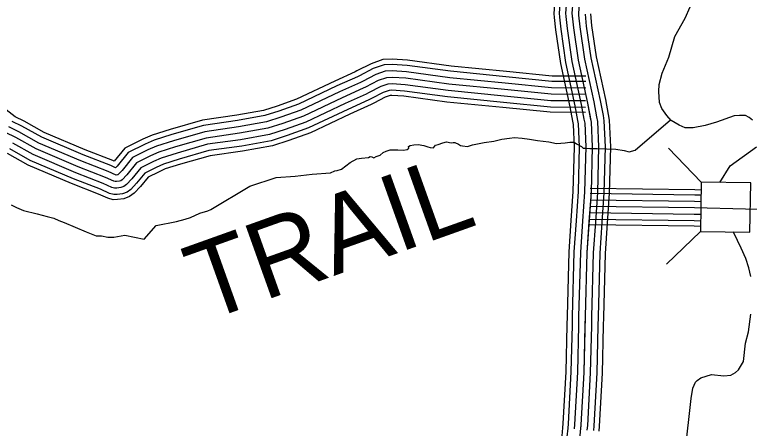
# Model space of a CAD drawing. Extents: x 1551132 to 1791609, y 378168 to 563823.
# Drawn here: x 1641403 to 1644933, y 435995 to 437985 of the extents above; entities that cross this region are included whole.
import ezdxf

# ---------------------------------------------------------------- set-up
doc = ezdxf.new("R2010")
doc.units = 0
for name, color, linetype in [('DESIGN - ROW - Right-of-Way and Easement Labels', 7, 'Continuous'), ('DESIGN - TRANSPORTATION - Text', 7, 'Continuous'), ('SURVEY - CONTROL with Text', 7, 'Continuous'), ('SURVEY - DRAINAGE - Storm Sewer', 7, 'Continuous'), ('SURVEY - TRANSPORTATION - Roads', 7, 'Continuous')]:
    doc.layers.add(name, color=color, linetype=linetype)

msp = doc.modelspace()

# ---------------------------------------------------------------- linework, layer by layer
at = {"layer": 'DESIGN - TRANSPORTATION - Text'}
for points in [[(1644947.992, 437477.501), (1644932.168, 437489.718), (1644914.31, 437499.96), (1644886.335, 437500.319), (1644860.328, 437498.644), (1644775.988, 437467.651), (1644721.823, 437452.309), (1644663.724, 437441.017), (1644624.683, 437441.342), (1644595.934, 437453.892), (1644558.251, 437476.409), (1644536.585, 437500.718), (1644513.019, 437533.069), (1644501.42, 437563.262), (1644498.095, 437615.388), (1644500.536, 437649.414), (1644515.219, 437703.315), (1644546.21, 437781.051), (1644575.476, 437880.845), (1644624.575, 437968.372), (1644649.258, 438022.149)], [(1642345.145, 437047.822), (1642533.14, 437159.633), (1642659.146, 437201.435), (1642751.11, 437208.435), (1642833.108, 437217.543), (1642921.073, 437224.585), (1642941.156, 437234.377), (1642953.164, 437236.252), (1642973.205, 437242.036), (1643015.504, 437273.612), (1643047.653, 437291.279), (1643069.67, 437295.046), (1643103.669, 437298.679), (1643111.702, 437302.596), (1643119.668, 437300.504), (1643129.61, 437296.387), (1643139.66, 437302.287), (1643159.726, 437310.071), (1643173.842, 437321.938), (1643187.884, 437327.788), (1643207.95, 437335.58), (1643243.899, 437335.18), (1643271.832, 437332.872), (1643289.856, 437336.68), (1643297.914, 437342.597), (1643296.006, 437350.63), (1643304.056, 437356.547), (1643322.055, 437358.356), (1643342.047, 437360.131), (1643369.963, 437355.822), (1643387.871, 437349.614), (1643399.812, 437345.48), (1643415.787, 437345.305), (1643425.911, 437357.206), (1643437.936, 437361.081), (1643459.994, 437368.848), (1643478.018, 437372.656), (1643499.943, 437368.406), (1643509.951, 437370.298), (1643517.934, 437370.214), (1643535.825, 437362.006), (1643545.742, 437355.889), (1643555.708, 437353.772), (1643579.649, 437351.506), (1643603.707, 437359.256), (1643659.764, 437370.648), (1643705.763, 437376.156), (1643743.821, 437385.748), (1643781.836, 437391.34), (1643805.844, 437395.074), (1643841.752, 437390.673), (1643877.659, 437386.273), (1643915.533, 437379.848), (1643969.399, 437373.248), (1644007.256, 437364.823), (1644049.238, 437368.365), (1644071.255, 437372.123), (1644081.238, 437372.015), (1644091.221, 437371.906), (1644103.12, 437363.765), (1644126.953, 437351.489), (1644134.853, 437343.389), (1644144.836, 437343.281), (1644166.786, 437341.031), (1644202.735, 437340.639), (1644292.583, 437337.647), (1644332.457, 437331.197), (1644356.356, 437324.922), (1644384.414, 437332.631), (1644555.368, 437479.651)], [(1644792.537, 437178.093), (1644841.195, 437257.546), (1644967.742, 437348.865)], [(1641386.626, 437070.397), (1641412.458, 437058.097), (1641446.249, 437043.705), (1641511.981, 437026.954), (1641559.78, 437014.412), (1641591.646, 437006.054), (1641615.495, 436995.779), (1641641.353, 436985.478), (1641746.709, 436940.261), (1641794.441, 436921.71), (1641820.407, 436921.427), (1641850.298, 436915.085), (1641880.256, 436914.76), (1641932.296, 436924.194), (1642025.961, 436905.143), (1642082.618, 436970.603), (1642180.707, 436989.554), (1642222.781, 437001.104), (1642248.839, 437008.829), (1642293.021, 437030.372), (1642331.103, 437041.964), (1642345.145, 437047.822)], [(1644940.8, 436726.44), (1644931.684, 436767.491), (1644915.934, 436812.892), (1644894.577, 436861.244), (1644859.569, 436935.804), (1644857.786, 436939.921)], [(1644573.383, 435671.346), (1644587.891, 435695.78), (1644601.258, 435732.914), (1644621.732, 435855.034), (1644642.074, 436037.08), (1644653.39, 436139.099), (1644662.032, 436189.076), (1644674.381, 436216.968), (1644682.481, 436224.877), (1644700.647, 436238.669), (1644751.988, 436253.544), (1644810.687, 436247.294), (1644844.702, 436250.878), (1644866.869, 436264.62), (1644881.01, 436276.462), (1644891.21, 436292.354), (1644905.509, 436316.213), (1644914.643, 436404.248), (1644929.359, 436460.15), (1644940.434, 436544.152)]]:
    msp.add_lwpolyline(points, dxfattribs=at)
at = {"layer": 'SURVEY - CONTROL with Text'}
for points in [[(1644109.854, 438485.027), (1644094.696, 438421.709), (1644029.248, 438218.22), (1644004.156, 438116.534), (1643994.123, 437991.381), (1643996.298, 437970.98)], [(1644133.887, 438479.269), (1644118.512, 438415.042), (1644053.039, 438211.47), (1644028.631, 438112.559), (1644018.939, 437991.706), (1644020.873, 437973.597)], [(1644164.036, 438472.052), (1644148.387, 438406.675), (1644082.88, 438202.995), (1644059.33, 438107.567), (1644050.072, 437992.114), (1644051.697, 437976.881)], [(1644194.186, 438464.835), (1644178.261, 438398.308), (1644112.721, 438194.528), (1644090.029, 438102.584), (1644081.205, 437992.523), (1644082.521, 437980.164)], [(1644224.335, 438457.618), (1644208.135, 438389.942), (1644142.562, 438186.061), (1644120.729, 438097.6), (1644112.337, 437992.931), (1644113.346, 437983.447)], [(1644081.205, 437992.523), (1644088.688, 437922.396), (1644111.529, 437766.067), (1644156.011, 437559.536), (1644173.327, 437467.309), (1644178.452, 437349.148), (1644172.819, 437130.942), (1644152.652, 436840.759), (1644144.352, 436532.476), (1644138.352, 436264.219), (1644124.469, 436012.038), (1644117.961, 435944.011), (1644097.378, 435866.059), (1644022.263, 435720.413), (1643900.491, 435488.999), (1643734.178, 435185.799), (1643563.807, 434876.632), (1643450.143, 434659.168), (1643287.83, 434355.952), (1643109.234, 434016.801), (1642955.02, 433727.535), (1642790.616, 433412.319), (1642721.592, 433278.648), (1642679.16, 433222.872)], [(1643996.298, 437970.98), (1644002.64, 437911.521), (1644026.147, 437750.65), (1644070.996, 437542.403), (1644084.196, 437472.134)], [(1644020.873, 437973.597), (1644027.164, 437914.621), (1644050.48, 437755.041), (1644095.229, 437547.286), (1644108.487, 437476.701)], [(1644051.697, 437976.889), (1644057.93, 437918.512), (1644081.004, 437760.558), (1644125.62, 437553.411), (1644138.953, 437482.418)], [(1644082.521, 437980.181), (1644088.688, 437922.396), (1644111.529, 437766.067), (1644156.011, 437559.536), (1644169.419, 437488.143)], [(1644113.346, 437983.472), (1644119.445, 437926.279), (1644142.053, 437771.575), (1644186.402, 437565.662), (1644199.885, 437493.868)], [(1644144.17, 437986.764), (1644150.211, 437930.171), (1644172.577, 437777.092), (1644216.793, 437571.787), (1644230.351, 437499.585)], [(1644169.744, 437989.489), (1644175.727, 437933.396), (1644197.893, 437781.659), (1644242.001, 437576.87), (1644255.625, 437504.335)], [(1644108.479, 437476.709), (1644111.579, 437460.209), (1644116.42, 437348.606), (1644110.878, 437133.892), (1644101.112, 436993.338)], [(1644138.945, 437482.434), (1644142.453, 437463.759), (1644147.436, 437348.873), (1644141.844, 437132.417), (1644132.036, 436991.188)], [(1644169.411, 437488.16), (1644173.327, 437467.309), (1644178.452, 437349.148), (1644172.819, 437130.942), (1644162.96, 436989.038)], [(1644199.877, 437493.885), (1644204.201, 437470.859), (1644209.468, 437349.423), (1644203.793, 437129.467), (1644193.885, 436986.888)], [(1644230.343, 437499.61), (1644235.076, 437474.409), (1644240.484, 437349.689), (1644234.759, 437127.992), (1644224.809, 436984.738)], [(1644255.617, 437504.352), (1644260.692, 437477.359), (1644266.217, 437349.914), (1644260.458, 437126.767), (1644250.467, 436982.955)], [(1644084.188, 437472.151), (1644086.963, 437457.375), (1644091.687, 437348.389), (1644086.179, 437135.067), (1644076.454, 436995.047)], [(1644076.454, 436995.072), (1644066.021, 436844.934), (1644057.663, 436534.61), (1644056.704, 436491.45)], [(1644101.112, 436993.355), (1644090.712, 436843.743), (1644082.37, 436534.001), (1644081.412, 436490.9)], [(1644132.036, 436991.205), (1644121.678, 436842.251), (1644113.361, 436533.243), (1644112.403, 436490.208)], [(1644162.96, 436989.055), (1644152.652, 436840.759), (1644144.352, 436532.476), (1644143.394, 436489.517)], [(1644193.885, 436986.905), (1644183.627, 436839.268), (1644175.343, 436531.71), (1644174.385, 436488.825)], [(1644224.809, 436984.755), (1644214.593, 436837.776), (1644206.334, 436530.951), (1644205.376, 436488.133)], [(1644250.467, 436982.971), (1644240.284, 436836.534), (1644232.042, 436530.318), (1644231.084, 436487.558)], [(1644056.704, 436491.475), (1644051.688, 436267.578), (1644037.98, 436018.546), (1644036.046, 435998.312)], [(1644081.412, 436490.917), (1644076.395, 436266.619), (1644062.629, 436016.696), (1644060.654, 435995.962)], [(1644112.403, 436490.225), (1644107.37, 436265.419), (1644093.553, 436014.363), (1644091.512, 435993.012)], [(1644143.394, 436489.533), (1644138.352, 436264.219), (1644124.469, 436012.038), (1644122.369, 435990.062)], [(1644174.385, 436488.842), (1644169.335, 436263.019), (1644155.385, 436009.712), (1644153.227, 435987.112)], [(1644205.376, 436488.15), (1644200.309, 436261.819), (1644186.309, 436007.379), (1644184.084, 435984.162)], [(1644231.084, 436487.575), (1644226.017, 436260.827), (1644211.95, 436005.454), (1644209.684, 435981.72)], [(1644036.046, 435998.337), (1644032.313, 435959.311), (1644015.963, 435897.376), (1643945.357, 435760.481), (1643848.092, 435575.634)], [(1644060.654, 435995.987), (1644056.729, 435954.953), (1644039.163, 435888.451), (1643967.281, 435749.064), (1643869.967, 435564.126)]]:
    msp.add_lwpolyline(points, dxfattribs=at)
at = {"layer": 'SURVEY - DRAINAGE - Storm Sewer'}
for p, q in [((1644702.417, 437179.963), (1644544.637, 437343.334)), ((1644698.281, 436942.395), (1644534.901, 436784.616))]:
    msp.add_line(p, q, dxfattribs=at)
msp.add_lwpolyline([(1644698.281, 436942.395), (1644935.84, 436938.26), (1644939.984, 437175.819), (1644702.417, 437179.963)], close=True, dxfattribs=at)
at = {"layer": 'SURVEY - TRANSPORTATION - Roads'}
for points in [[(1644147.511, 437689.056), (1643985.957, 437689.981), (1643766.354, 437711.749), (1643500.285, 437738.174), (1643291.398, 437766.366), (1643216.65, 437771.625), (1643173.159, 437768.7), (1643116.094, 437749.291), (1643047.587, 437714.173), (1643039.237, 437709.673), (1642940.948, 437665.522), (1642757.31, 437578.669), (1642664.354, 437545.469), (1642598.981, 437524.335), (1642470.275, 437500.959), (1642305.763, 437477.85), (1642150.425, 437433.199), (1642064.06, 437405.99), (1642019.153, 437385.547), (1641932.946, 437343.013), (1641881.831, 437279.711), (1641874.831, 437282.953), (1641742.076, 437334.788), (1641544.739, 437418.415), (1641449.499, 437472.183), (1641405.292, 437493.966), (1641283.037, 437587.677)], [(1644147.37, 437663.339), (1643984.615, 437664.272), (1643763.82, 437686.156), (1643497.293, 437712.632), (1643288.773, 437740.774), (1643216.608, 437745.849), (1643178.251, 437743.266), (1643126.152, 437725.549), (1643059.562, 437691.414), (1643050.62, 437686.597), (1642951.714, 437642.163), (1642767.152, 437554.877), (1642672.629, 437521.118), (1642605.256, 437499.342), (1642474.359, 437475.567), (1642311.129, 437452.633), (1642157.841, 437408.565), (1642073.285, 437381.931), (1642030.169, 437362.313), (1641949.396, 437322.454), (1641895.897, 437256.202), (1641888.397, 437248.344), (1641864.748, 437259.277), (1641732.376, 437310.97), (1641533.364, 437395.306), (1641437.491, 437449.44), (1641391.659, 437472.016)], [(1644147.186, 437632.338), (1643982.998, 437633.28), (1643760.754, 437655.305), (1643493.685, 437681.831), (1643285.615, 437709.923), (1643216.566, 437714.773), (1643184.384, 437712.607), (1643138.277, 437696.923), (1643073.986, 437663.972), (1643064.345, 437658.772), (1642964.697, 437614.004), (1642779.027, 437526.193), (1642682.612, 437491.759), (1642612.83, 437469.208), (1642479.292, 437444.949), (1642317.604, 437422.232), (1642166.782, 437378.881), (1642084.401, 437352.93), (1642043.452, 437334.296), (1641969.229, 437297.67), (1641919.205, 437235.727), (1641899.322, 437214.884), (1641897.972, 437213.909), (1641891.164, 437213.251), (1641890.464, 437213.234), (1641852.59, 437230.743), (1641720.693, 437282.253), (1641519.648, 437367.447), (1641423.008, 437422.015), (1641375.218, 437445.557)], [(1644147.011, 437601.337), (1643981.373, 437602.287), (1643757.695, 437624.455), (1643490.077, 437651.038), (1643282.448, 437679.064), (1643216.516, 437683.697), (1643190.517, 437681.947), (1643150.401, 437668.305), (1643088.411, 437636.529), (1643078.07, 437630.954), (1642977.672, 437585.853), (1642790.893, 437497.517), (1642692.595, 437462.408), (1642620.397, 437439.074), (1642484.217, 437414.34), (1642324.07, 437391.839), (1642175.724, 437349.196), (1642095.517, 437323.929), (1642056.735, 437306.279), (1641989.062, 437272.886), (1641942.521, 437215.251), (1641919.788, 437191.426), (1641912.638, 437186.259), (1641906.23, 437183.559), (1641892.939, 437182.275), (1641886.489, 437182.159), (1641880.239, 437183.809), (1641840.44, 437202.209), (1641709.001, 437253.535), (1641505.94, 437339.588), (1641408.525, 437394.589), (1641358.785, 437419.098)], [(1644147.011, 437601.337), (1643981.373, 437602.287), (1643757.695, 437624.455), (1643490.077, 437651.038), (1643282.448, 437679.064), (1643216.516, 437683.697), (1643190.517, 437681.947), (1643150.401, 437668.305), (1643088.411, 437636.529), (1643078.07, 437630.954), (1642977.672, 437585.853), (1642790.893, 437497.517), (1642692.595, 437462.408), (1642620.397, 437439.074), (1642484.217, 437414.34), (1642324.07, 437391.839), (1642175.724, 437349.196), (1642095.517, 437323.929), (1642056.735, 437306.279), (1641989.062, 437272.886), (1641942.521, 437215.251), (1641919.788, 437191.426), (1641912.638, 437186.259), (1641906.23, 437183.559), (1641892.939, 437182.275), (1641886.489, 437182.159), (1641880.239, 437183.809), (1641840.44, 437202.209), (1641709.001, 437253.535), (1641505.94, 437339.588), (1641408.525, 437394.589), (1641358.785, 437419.098)], [(1644146.836, 437570.337), (1643979.748, 437571.295), (1643754.637, 437593.604), (1643486.468, 437620.246), (1643279.282, 437648.205), (1643216.466, 437652.622), (1643196.65, 437651.288), (1643162.526, 437639.688), (1643102.836, 437609.087), (1643091.794, 437603.137), (1642990.647, 437557.702), (1642802.759, 437468.842), (1642702.578, 437433.057), (1642627.963, 437408.94), (1642489.142, 437383.731), (1642330.537, 437361.447), (1642184.665, 437319.512), (1642106.634, 437294.928), (1642070.018, 437278.261), (1642008.894, 437248.102), (1641965.837, 437194.776), (1641940.254, 437167.967), (1641927.93, 437159.058), (1641913.913, 437153.158), (1641894.714, 437151.299), (1641882.739, 437151.083), (1641869.698, 437154.525), (1641828.29, 437173.675), (1641697.31, 437224.818), (1641492.232, 437311.728), (1641394.042, 437367.163)], [(1644146.653, 437539.336), (1643978.132, 437540.302), (1643751.57, 437562.753), (1643482.86, 437589.445), (1643276.123, 437617.354), (1643216.425, 437621.546), (1643202.783, 437620.629), (1643174.651, 437611.062), (1643117.26, 437581.645), (1643105.519, 437575.311), (1643003.63, 437529.543), (1642814.634, 437440.158), (1642712.561, 437403.698), (1642635.538, 437378.806), (1642494.075, 437353.113), (1642337.012, 437331.046), (1642193.607, 437289.828), (1642117.75, 437265.928), (1642083.301, 437250.244), (1642028.727, 437223.318), (1641989.145, 437174.3), (1641960.712, 437144.508), (1641943.221, 437131.866), (1641921.596, 437122.749), (1641896.48, 437120.324), (1641878.997, 437120.015), (1641859.156, 437125.249), (1641816.132, 437145.141), (1641685.627, 437196.101), (1641478.515, 437283.869), (1641379.559, 437339.737)], [(1644146.511, 437514.619), (1643976.84, 437515.593), (1643749.137, 437538.161), (1643479.985, 437564.895), (1643273.598, 437592.753), (1643216.391, 437596.77), (1643207.675, 437596.187), (1643184.317, 437588.245), (1643128.768, 437559.769), (1643116.46, 437553.136), (1643013.979, 437507.093), (1642824.092, 437417.29), (1642720.52, 437380.298), (1642641.571, 437354.78), (1642498, 437328.704), (1642342.17, 437306.812), (1642200.732, 437266.153), (1642126.617, 437242.81), (1642093.884, 437227.91), (1642044.535, 437203.559), (1642007.736, 437157.983), (1641977.028, 437125.799), (1641955.412, 437110.182), (1641927.721, 437098.515), (1641897.897, 437095.631), (1641876.006, 437095.24), (1641850.756, 437101.906), (1641806.441, 437122.39), (1641676.311, 437173.208), (1641467.582, 437261.66), (1641368.018, 437317.879)], [(1644169.01, 437125.9), (1644670.957, 437118.992), (1644701.34, 437118.2)], [(1644169.352, 437150.617), (1644671.449, 437143.701), (1644701.781, 437142.917)], [(1644168.585, 437094.908), (1644670.34, 437087.991), (1644700.823, 437087.199)], [(1644168.16, 437063.907), (1644669.724, 437056.999), (1645159.37, 437044.298), (1645415.231, 437041.857), (1645675.183, 437049.382), (1646019.092, 437056.108), (1646506.956, 437065.458), (1647160.774, 437077.234), (1647442.717, 437084.542)], [(1644168.16, 437063.907), (1644669.724, 437056.999), (1644700.273, 437056.207)], [(1644167.735, 437032.906), (1644669.107, 437026.006), (1644699.74, 437025.214)], [(1644167.31, 437001.913), (1644668.49, 436995.005), (1644699.173, 436994.214)], [(1644166.952, 436976.196), (1644667.982, 436969.296), (1644698.723, 436968.496)]]:
    msp.add_lwpolyline(points, dxfattribs=at)

# ---------------------------------------------------------------- texts
at = {"layer": 'DESIGN - ROW - Right-of-Way and Easement Labels'}
msp.add_text('TRAIL', height=369.9935, rotation=19.655042, dxfattribs=at).set_placement((1642314.81, 436505.883))

doc.saveas('drawing.dxf')
